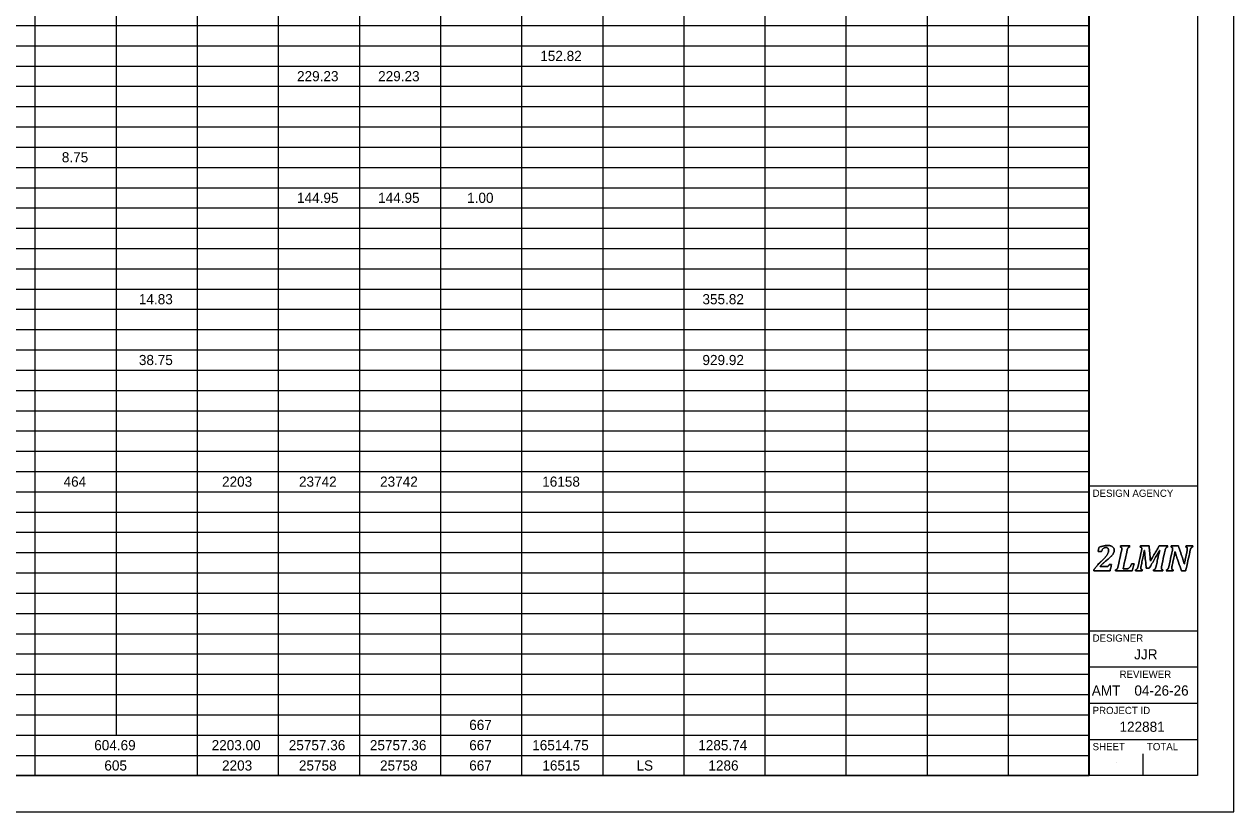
# Model space of a CAD drawing. Extents: x 0 to 34, y 0 to 22.
# Drawn here: x 17.3 to 34, y 0 to 10.88 of the extents above; entities that cross this region are included whole.
import ezdxf

# ---------------------------------------------------------------- set-up
doc = ezdxf.new("R2010")
doc.units = 0
for name, color, linetype in [('SH_Border', 7, 'Continuous'), ('SH_Cut_Line', 7, 'Continuous'), ('SH_Data', 7, 'Continuous'), ('SH_Text', 7, 'Continuous')]:
    doc.layers.add(name, color=color, linetype=linetype)

msp = doc.modelspace()

# ---------------------------------------------------------------- linework, layer by layer
at = {"layer": 'SH_Border'}
for p, q in [((32, 0.5), (32, 21.5)), ((32, 4.5), (33.5, 4.5)), ((32, 2.5), (33.5, 2.5)), ((32, 2), (33.5, 2)), ((32, 1.5), (33.5, 1.5)), ((32, 1), (33.5, 1))]:
    msp.add_line(p, q, dxfattribs=at)
msp.add_lwpolyline([(1.5, 21.5), (33.5, 21.5), (33.5, 0.5), (1.5, 0.5)], close=True, dxfattribs=at)
at = {"layer": 'SH_Cut_Line'}
msp.add_lwpolyline([(0, 0), (34, 0), (34, 22), (0, 22)], close=True, dxfattribs=at)
at = {"layer": 'SH_Data'}
for p, q in [((32.75, 3.5), (32.75, 3.5)), ((32.375, 0.675), (32.375, 0.675)), ((32.75, 0.5), (32.75, 0.8))]:
    msp.add_line(p, q, dxfattribs=at)
for points in [[(32.237, 3.388), (32.246, 3.388), (32.253, 3.389), (32.258, 3.39), (32.263, 3.392), (32.267, 3.394), (32.27, 3.397), (32.273, 3.401), (32.277, 3.408), (32.281, 3.417), (32.281, 3.417), (32.312, 3.417), (32.312, 3.417), (32.312, 3.417), (32.29, 3.326), (32.29, 3.326), (32.29, 3.326), (32.066, 3.326), (32.066, 3.326), (32.066, 3.326), (32.069, 3.343), (32.069, 3.343), (32.078, 3.358), (32.091, 3.375), (32.106, 3.394), (32.122, 3.412), (32.144, 3.435), (32.172, 3.462), (32.197, 3.486), (32.217, 3.506), (32.23, 3.521), (32.243, 3.537), (32.253, 3.551), (32.259, 3.566), (32.266, 3.58), (32.269, 3.595), (32.269, 3.61), (32.269, 3.622), (32.266, 3.632), (32.26, 3.64), (32.253, 3.647), (32.245, 3.65), (32.234, 3.65), (32.22, 3.65), (32.208, 3.646), (32.198, 3.636), (32.188, 3.627), (32.18, 3.613), (32.172, 3.593), (32.172, 3.593), (32.126, 3.593), (32.126, 3.593), (32.126, 3.593), (32.14, 3.654), (32.14, 3.654), (32.166, 3.663), (32.188, 3.669), (32.205, 3.673), (32.223, 3.676), (32.24, 3.678), (32.258, 3.678), (32.278, 3.678), (32.295, 3.675), (32.309, 3.669), (32.322, 3.664), (32.332, 3.656), (32.339, 3.646), (32.345, 3.637), (32.348, 3.626), (32.348, 3.613), (32.348, 3.602), (32.346, 3.591), (32.342, 3.581), (32.339, 3.571), (32.333, 3.56), (32.324, 3.549), (32.315, 3.539), (32.304, 3.526), (32.289, 3.513), (32.275, 3.499), (32.254, 3.482), (32.228, 3.46), (32.216, 3.45), (32.202, 3.438), (32.188, 3.425), (32.174, 3.412), (32.162, 3.4), (32.154, 3.391), (32.154, 3.391), (32.153, 3.388), (32.153, 3.388), (32.153, 3.388), (32.237, 3.388), (32.237, 3.388)], [(32.237, 3.388), (32.237, 3.388), (32.153, 3.388), (32.153, 3.388), (32.153, 3.388), (32.154, 3.391), (32.154, 3.391), (32.162, 3.4), (32.174, 3.412), (32.188, 3.425), (32.202, 3.438), (32.216, 3.45), (32.228, 3.46), (32.254, 3.482), (32.275, 3.499), (32.289, 3.513), (32.304, 3.526), (32.315, 3.539), (32.324, 3.549), (32.333, 3.56), (32.339, 3.571), (32.342, 3.581), (32.346, 3.591), (32.348, 3.602), (32.348, 3.613), (32.348, 3.626), (32.345, 3.637), (32.339, 3.646), (32.332, 3.656), (32.322, 3.664), (32.309, 3.669), (32.295, 3.675), (32.278, 3.678), (32.258, 3.678), (32.24, 3.678), (32.223, 3.676), (32.205, 3.673), (32.188, 3.669), (32.166, 3.663), (32.14, 3.654), (32.14, 3.654), (32.126, 3.593), (32.126, 3.593), (32.126, 3.593), (32.172, 3.593), (32.172, 3.593), (32.18, 3.613), (32.188, 3.627), (32.198, 3.636), (32.208, 3.646), (32.22, 3.65), (32.234, 3.65), (32.245, 3.65), (32.253, 3.647), (32.26, 3.64), (32.266, 3.632), (32.269, 3.622), (32.269, 3.61), (32.269, 3.595), (32.266, 3.58), (32.259, 3.566), (32.253, 3.551), (32.243, 3.537), (32.23, 3.521), (32.217, 3.506), (32.197, 3.486), (32.172, 3.462), (32.144, 3.435), (32.122, 3.412), (32.106, 3.394), (32.091, 3.375), (32.078, 3.358), (32.069, 3.343), (32.069, 3.343), (32.066, 3.326), (32.066, 3.326), (32.066, 3.326), (32.29, 3.326), (32.29, 3.326), (32.29, 3.326), (32.312, 3.417), (32.312, 3.417), (32.312, 3.417), (32.281, 3.417), (32.281, 3.417), (32.277, 3.408), (32.273, 3.401), (32.27, 3.397), (32.267, 3.394), (32.263, 3.392), (32.258, 3.39), (32.253, 3.389), (32.246, 3.388), (32.237, 3.388)], [(32.518, 3.356), (32.527, 3.356), (32.533, 3.357), (32.538, 3.358), (32.542, 3.36), (32.546, 3.362), (32.55, 3.365), (32.554, 3.368), (32.558, 3.372), (32.562, 3.377), (32.567, 3.382), (32.571, 3.388), (32.576, 3.397), (32.58, 3.405), (32.585, 3.415), (32.589, 3.427), (32.589, 3.427), (32.624, 3.427), (32.624, 3.427), (32.624, 3.427), (32.598, 3.326), (32.598, 3.326), (32.598, 3.326), (32.365, 3.326), (32.365, 3.326), (32.365, 3.326), (32.369, 3.343), (32.369, 3.343), (32.376, 3.345), (32.381, 3.348), (32.385, 3.351), (32.389, 3.355), (32.392, 3.36), (32.395, 3.366), (32.398, 3.373), (32.4, 3.382), (32.403, 3.395), (32.403, 3.395), (32.449, 3.605), (32.449, 3.605), (32.452, 3.615), (32.453, 3.625), (32.453, 3.635), (32.453, 3.642), (32.451, 3.647), (32.448, 3.651), (32.444, 3.654), (32.439, 3.656), (32.432, 3.657), (32.432, 3.657), (32.435, 3.674), (32.435, 3.674), (32.435, 3.674), (32.563, 3.674), (32.563, 3.674), (32.563, 3.674), (32.559, 3.657), (32.559, 3.657), (32.552, 3.655), (32.547, 3.652), (32.543, 3.649), (32.539, 3.645), (32.536, 3.64), (32.533, 3.634), (32.531, 3.627), (32.528, 3.618), (32.525, 3.605), (32.525, 3.605), (32.47, 3.356), (32.47, 3.356), (32.47, 3.356), (32.518, 3.356), (32.518, 3.356)], [(32.518, 3.356), (32.518, 3.356), (32.47, 3.356), (32.47, 3.356), (32.47, 3.356), (32.525, 3.605), (32.525, 3.605), (32.528, 3.618), (32.531, 3.627), (32.533, 3.634), (32.536, 3.64), (32.539, 3.645), (32.543, 3.649), (32.547, 3.652), (32.552, 3.655), (32.559, 3.657), (32.559, 3.657), (32.563, 3.674), (32.563, 3.674), (32.563, 3.674), (32.435, 3.674), (32.435, 3.674), (32.435, 3.674), (32.432, 3.657), (32.432, 3.657), (32.439, 3.656), (32.444, 3.654), (32.448, 3.651), (32.451, 3.647), (32.453, 3.642), (32.453, 3.635), (32.453, 3.625), (32.452, 3.615), (32.449, 3.605), (32.449, 3.605), (32.403, 3.395), (32.403, 3.395), (32.4, 3.382), (32.398, 3.373), (32.395, 3.366), (32.392, 3.36), (32.389, 3.355), (32.385, 3.351), (32.381, 3.348), (32.376, 3.345), (32.369, 3.343), (32.369, 3.343), (32.365, 3.326), (32.365, 3.326), (32.365, 3.326), (32.598, 3.326), (32.598, 3.326), (32.598, 3.326), (32.624, 3.427), (32.624, 3.427), (32.624, 3.427), (32.589, 3.427), (32.589, 3.427), (32.585, 3.415), (32.58, 3.405), (32.576, 3.397), (32.571, 3.388), (32.567, 3.382), (32.562, 3.377), (32.558, 3.372), (32.554, 3.368), (32.55, 3.365), (32.546, 3.362), (32.542, 3.36), (32.538, 3.358), (32.533, 3.357), (32.527, 3.356), (32.518, 3.356)], [(32.829, 3.674), (32.829, 3.674), (32.849, 3.461), (32.849, 3.461), (32.849, 3.461), (32.969, 3.674), (32.969, 3.674), (32.969, 3.674), (33.087, 3.674), (33.087, 3.674), (33.087, 3.674), (33.084, 3.657), (33.084, 3.657), (33.077, 3.655), (33.071, 3.652), (33.067, 3.649), (33.064, 3.645), (33.06, 3.64), (33.058, 3.634), (33.055, 3.627), (33.052, 3.618), (33.05, 3.605), (33.05, 3.605), (33.003, 3.395), (33.003, 3.395), (33.002, 3.39), (33.002, 3.387), (33.001, 3.384), (33.001, 3.382), (33.001, 3.379), (33, 3.376), (33, 3.373), (33, 3.369), (33, 3.365), (33, 3.358), (33.002, 3.353), (33.005, 3.349), (33.008, 3.346), (33.014, 3.344), (33.021, 3.343), (33.021, 3.343), (33.018, 3.326), (33.018, 3.326), (33.018, 3.326), (32.89, 3.326), (32.89, 3.326), (32.89, 3.326), (32.893, 3.343), (32.893, 3.343), (32.9, 3.345), (32.906, 3.348), (32.91, 3.351), (32.914, 3.355), (32.917, 3.36), (32.919, 3.366), (32.922, 3.373), (32.925, 3.382), (32.928, 3.395), (32.928, 3.395), (32.951, 3.502), (32.951, 3.502), (32.954, 3.513), (32.957, 3.529), (32.962, 3.548), (32.967, 3.568), (32.972, 3.588), (32.978, 3.609), (32.978, 3.609), (32.973, 3.609), (32.973, 3.609), (32.965, 3.594), (32.957, 3.579), (32.948, 3.563), (32.948, 3.563), (32.833, 3.364), (32.833, 3.364), (32.833, 3.364), (32.792, 3.364), (32.792, 3.364), (32.792, 3.364), (32.775, 3.518), (32.775, 3.518), (32.773, 3.537), (32.772, 3.554), (32.77, 3.569), (32.769, 3.583), (32.768, 3.597), (32.768, 3.611), (32.768, 3.611), (32.764, 3.611), (32.764, 3.611), (32.761, 3.596), (32.758, 3.578), (32.755, 3.558), (32.751, 3.538), (32.747, 3.521), (32.744, 3.507), (32.744, 3.507), (32.72, 3.395), (32.72, 3.395), (32.719, 3.39), (32.718, 3.387), (32.718, 3.384), (32.717, 3.382), (32.717, 3.379), (32.717, 3.376), (32.717, 3.373), (32.716, 3.369), (32.716, 3.365), (32.716, 3.358), (32.718, 3.353), (32.721, 3.349), (32.725, 3.346), (32.73, 3.344), (32.738, 3.343), (32.738, 3.343), (32.734, 3.326), (32.734, 3.326), (32.734, 3.326), (32.641, 3.326), (32.641, 3.326), (32.641, 3.326), (32.644, 3.343), (32.644, 3.343), (32.651, 3.345), (32.657, 3.348), (32.661, 3.351), (32.665, 3.355), (32.668, 3.36), (32.67, 3.366), (32.673, 3.373), (32.676, 3.382), (32.679, 3.395), (32.679, 3.395), (32.725, 3.605), (32.725, 3.605), (32.727, 3.615), (32.728, 3.625), (32.728, 3.635), (32.728, 3.642), (32.727, 3.647), (32.723, 3.651), (32.72, 3.654), (32.715, 3.656), (32.707, 3.657), (32.707, 3.657), (32.711, 3.674), (32.711, 3.674), (32.711, 3.674), (32.829, 3.674), (32.829, 3.674)], [(32.829, 3.674), (32.829, 3.674), (32.711, 3.674), (32.711, 3.674), (32.711, 3.674), (32.707, 3.657), (32.707, 3.657), (32.715, 3.656), (32.72, 3.654), (32.723, 3.651), (32.727, 3.647), (32.728, 3.642), (32.728, 3.635), (32.728, 3.625), (32.727, 3.615), (32.725, 3.605), (32.725, 3.605), (32.679, 3.395), (32.679, 3.395), (32.676, 3.382), (32.673, 3.373), (32.67, 3.366), (32.668, 3.36), (32.665, 3.355), (32.661, 3.351), (32.657, 3.348), (32.651, 3.345), (32.644, 3.343), (32.644, 3.343), (32.641, 3.326), (32.641, 3.326), (32.641, 3.326), (32.734, 3.326), (32.734, 3.326), (32.734, 3.326), (32.738, 3.343), (32.738, 3.343), (32.73, 3.344), (32.725, 3.346), (32.721, 3.349), (32.718, 3.353), (32.716, 3.358), (32.716, 3.365), (32.716, 3.369), (32.717, 3.373), (32.717, 3.376), (32.717, 3.379), (32.717, 3.382), (32.718, 3.384), (32.718, 3.387), (32.719, 3.39), (32.72, 3.395), (32.72, 3.395), (32.744, 3.507), (32.744, 3.507), (32.747, 3.521), (32.751, 3.538), (32.755, 3.558), (32.758, 3.578), (32.761, 3.596), (32.764, 3.611), (32.764, 3.611), (32.768, 3.611), (32.768, 3.611), (32.768, 3.597), (32.769, 3.583), (32.77, 3.569), (32.772, 3.554), (32.773, 3.537), (32.775, 3.518), (32.775, 3.518), (32.792, 3.364), (32.792, 3.364), (32.792, 3.364), (32.833, 3.364), (32.833, 3.364), (32.833, 3.364), (32.948, 3.563), (32.948, 3.563), (32.957, 3.579), (32.965, 3.594), (32.973, 3.609), (32.973, 3.609), (32.978, 3.609), (32.978, 3.609), (32.972, 3.588), (32.967, 3.568), (32.962, 3.548), (32.957, 3.529), (32.954, 3.513), (32.951, 3.502), (32.951, 3.502), (32.928, 3.395), (32.928, 3.395), (32.925, 3.382), (32.922, 3.373), (32.919, 3.366), (32.917, 3.36), (32.914, 3.355), (32.91, 3.351), (32.906, 3.348), (32.9, 3.345), (32.893, 3.343), (32.893, 3.343), (32.89, 3.326), (32.89, 3.326), (32.89, 3.326), (33.018, 3.326), (33.018, 3.326), (33.018, 3.326), (33.021, 3.343), (33.021, 3.343), (33.014, 3.344), (33.008, 3.346), (33.005, 3.349), (33.002, 3.353), (33, 3.358), (33, 3.365), (33, 3.369), (33, 3.373), (33, 3.376), (33.001, 3.379), (33.001, 3.382), (33.001, 3.384), (33.002, 3.387), (33.002, 3.39), (33.003, 3.395), (33.003, 3.395), (33.05, 3.605), (33.05, 3.605), (33.052, 3.618), (33.055, 3.627), (33.058, 3.634), (33.06, 3.64), (33.064, 3.645), (33.067, 3.649), (33.071, 3.652), (33.077, 3.655), (33.084, 3.657), (33.084, 3.657), (33.087, 3.674), (33.087, 3.674), (33.087, 3.674), (32.969, 3.674), (32.969, 3.674), (32.969, 3.674), (32.849, 3.461), (32.849, 3.461), (32.849, 3.461), (32.829, 3.674), (32.829, 3.674)], [(33.137, 3.674), (33.137, 3.674), (33.234, 3.674), (33.234, 3.674), (33.234, 3.674), (33.283, 3.53), (33.283, 3.53), (33.296, 3.49), (33.307, 3.456), (33.315, 3.426), (33.315, 3.426), (33.318, 3.426), (33.318, 3.426), (33.323, 3.455), (33.329, 3.488), (33.337, 3.523), (33.337, 3.523), (33.355, 3.605), (33.355, 3.605), (33.357, 3.615), (33.358, 3.625), (33.358, 3.635), (33.358, 3.642), (33.357, 3.647), (33.353, 3.651), (33.35, 3.654), (33.345, 3.656), (33.337, 3.657), (33.337, 3.657), (33.341, 3.674), (33.341, 3.674), (33.341, 3.674), (33.434, 3.674), (33.434, 3.674), (33.434, 3.674), (33.431, 3.657), (33.431, 3.657), (33.424, 3.655), (33.418, 3.652), (33.414, 3.649), (33.41, 3.645), (33.407, 3.64), (33.405, 3.634), (33.402, 3.627), (33.399, 3.618), (33.396, 3.605), (33.396, 3.605), (33.335, 3.326), (33.335, 3.326), (33.335, 3.326), (33.277, 3.326), (33.277, 3.326), (33.277, 3.326), (33.216, 3.504), (33.216, 3.504), (33.211, 3.518), (33.207, 3.531), (33.204, 3.543), (33.2, 3.556), (33.195, 3.571), (33.19, 3.59), (33.19, 3.59), (33.186, 3.59), (33.186, 3.59), (33.185, 3.579), (33.182, 3.563), (33.179, 3.543), (33.175, 3.523), (33.17, 3.501), (33.165, 3.478), (33.165, 3.478), (33.147, 3.395), (33.147, 3.395), (33.146, 3.39), (33.145, 3.387), (33.145, 3.384), (33.144, 3.382), (33.144, 3.379), (33.144, 3.376), (33.143, 3.373), (33.143, 3.369), (33.143, 3.365), (33.143, 3.358), (33.145, 3.353), (33.148, 3.349), (33.152, 3.346), (33.157, 3.344), (33.164, 3.343), (33.164, 3.343), (33.161, 3.326), (33.161, 3.326), (33.161, 3.326), (33.067, 3.326), (33.067, 3.326), (33.067, 3.326), (33.071, 3.343), (33.071, 3.343), (33.078, 3.345), (33.083, 3.348), (33.087, 3.351), (33.091, 3.355), (33.094, 3.36), (33.097, 3.366), (33.1, 3.373), (33.102, 3.382), (33.105, 3.395), (33.105, 3.395), (33.151, 3.605), (33.151, 3.605), (33.154, 3.615), (33.155, 3.625), (33.155, 3.635), (33.155, 3.642), (33.153, 3.647), (33.15, 3.651), (33.146, 3.654), (33.141, 3.656), (33.134, 3.657), (33.134, 3.657), (33.137, 3.674), (33.137, 3.674)], [(33.137, 3.674), (33.137, 3.674), (33.134, 3.657), (33.134, 3.657), (33.141, 3.656), (33.146, 3.654), (33.15, 3.651), (33.153, 3.647), (33.155, 3.642), (33.155, 3.635), (33.155, 3.625), (33.154, 3.615), (33.151, 3.605), (33.151, 3.605), (33.105, 3.395), (33.105, 3.395), (33.102, 3.382), (33.1, 3.373), (33.097, 3.366), (33.094, 3.36), (33.091, 3.355), (33.087, 3.351), (33.083, 3.348), (33.078, 3.345), (33.071, 3.343), (33.071, 3.343), (33.067, 3.326), (33.067, 3.326), (33.067, 3.326), (33.161, 3.326), (33.161, 3.326), (33.161, 3.326), (33.164, 3.343), (33.164, 3.343), (33.157, 3.344), (33.152, 3.346), (33.148, 3.349), (33.145, 3.353), (33.143, 3.358), (33.143, 3.365), (33.143, 3.369), (33.143, 3.373), (33.144, 3.376), (33.144, 3.379), (33.144, 3.382), (33.145, 3.384), (33.145, 3.387), (33.146, 3.39), (33.147, 3.395), (33.147, 3.395), (33.165, 3.478), (33.165, 3.478), (33.17, 3.501), (33.175, 3.523), (33.179, 3.543), (33.182, 3.563), (33.185, 3.579), (33.186, 3.59), (33.186, 3.59), (33.19, 3.59), (33.19, 3.59), (33.195, 3.571), (33.2, 3.556), (33.204, 3.543), (33.207, 3.531), (33.211, 3.518), (33.216, 3.504), (33.216, 3.504), (33.277, 3.326), (33.277, 3.326), (33.277, 3.326), (33.335, 3.326), (33.335, 3.326), (33.335, 3.326), (33.396, 3.605), (33.396, 3.605), (33.399, 3.618), (33.402, 3.627), (33.405, 3.634), (33.407, 3.64), (33.41, 3.645), (33.414, 3.649), (33.418, 3.652), (33.424, 3.655), (33.431, 3.657), (33.431, 3.657), (33.434, 3.674), (33.434, 3.674), (33.434, 3.674), (33.341, 3.674), (33.341, 3.674), (33.341, 3.674), (33.337, 3.657), (33.337, 3.657), (33.345, 3.656), (33.35, 3.654), (33.353, 3.651), (33.357, 3.647), (33.358, 3.642), (33.358, 3.635), (33.358, 3.625), (33.357, 3.615), (33.355, 3.605), (33.355, 3.605), (33.337, 3.523), (33.337, 3.523), (33.329, 3.488), (33.323, 3.455), (33.318, 3.426), (33.318, 3.426), (33.315, 3.426), (33.315, 3.426), (33.307, 3.456), (33.296, 3.49), (33.283, 3.53), (33.283, 3.53), (33.234, 3.674), (33.234, 3.674), (33.234, 3.674), (33.137, 3.674), (33.137, 3.674)]]:
    msp.add_open_spline(points, degree=3, dxfattribs=at)
at = {"layer": 'SH_Text'}
for p, q in [((17.444, 21.5), (17.444, 0.5)), ((18.564, 21.5), (18.564, 1.06)), ((19.684, 21.5), (19.684, 0.5)), ((20.804, 21.5), (20.804, 0.5)), ((21.924, 21.5), (21.924, 0.5)), ((23.044, 21.5), (23.044, 0.5)), ((24.164, 21.5), (24.164, 0.5)), ((25.284, 21.5), (25.284, 0.5)), ((26.404, 21.5), (26.404, 0.5)), ((27.524, 21.5), (27.524, 0.5)), ((28.644, 21.5), (28.644, 0.5)), ((29.764, 21.5), (29.764, 0.5)), ((30.884, 21.5), (30.884, 0.5)), ((32.004, 21.5), (32.004, 0.5)), ((1.5, 10.86), (32.004, 10.86)), ((1.5, 10.58), (32.004, 10.58)), ((1.5, 10.3), (32.004, 10.3)), ((1.5, 10.02), (32.004, 10.02)), ((1.5, 9.74), (32.004, 9.74)), ((1.5, 9.46), (32.004, 9.46)), ((1.5, 9.18), (32.004, 9.18)), ((1.5, 8.9), (32.004, 8.9)), ((1.5, 8.62), (32.004, 8.62)), ((1.5, 8.34), (32.004, 8.34)), ((1.5, 8.06), (32.004, 8.06)), ((1.5, 7.78), (32.004, 7.78)), ((1.5, 7.5), (32.004, 7.5)), ((1.5, 7.22), (32.004, 7.22)), ((1.5, 6.94), (32.004, 6.94)), ((1.5, 6.66), (32.004, 6.66)), ((1.5, 6.38), (32.004, 6.38)), ((1.5, 6.1), (32.004, 6.1)), ((1.5, 5.82), (32.004, 5.82)), ((1.5, 5.54), (32.004, 5.54)), ((1.5, 5.26), (32.004, 5.26)), ((1.5, 4.98), (32.004, 4.98)), ((1.5, 4.7), (32.004, 4.7)), ((1.5, 4.42), (32.004, 4.42)), ((1.5, 4.14), (32.004, 4.14)), ((1.5, 3.86), (32.004, 3.86)), ((1.5, 3.58), (32.004, 3.58)), ((1.5, 3.3), (32.004, 3.3)), ((1.5, 3.02), (32.004, 3.02)), ((1.5, 2.74), (32.004, 2.74)), ((1.5, 2.46), (32.004, 2.46)), ((1.5, 2.18), (32.004, 2.18)), ((1.5, 1.9), (32.004, 1.9)), ((1.5, 1.62), (32.004, 1.62)), ((1.5, 1.34), (32.004, 1.34)), ((1.5, 1.06), (32.004, 1.06)), ((1.5, 0.78), (32.004, 0.78)), ((1.5, 0.5), (32.004, 0.5))]:
    msp.add_line(p, q, dxfattribs=at)

# ---------------------------------------------------------------- texts
at = {"layer": 'SH_Data'}
for s, height, p in [('DESIGN AGENCY', 0.1, (32.05, 4.35)), ('DESIGNER', 0.1, (32.05, 2.35)), ('JJR', 0.14, (32.624, 2.105)), ('REVIEWER', 0.1, (32.422, 1.85)), ('AMT', 0.14, (32.039, 1.605)), ('04-26-26', 0.14, (32.627, 1.605)), ('PROJECT ID', 0.1, (32.05, 1.35)), ('122881', 0.14, (32.421, 1.105)), ('SHEET', 0.1, (32.05, 0.85)), ('TOTAL', 0.1, (32.8, 0.85))]:
    msp.add_text(s, height=height, dxfattribs=at).set_placement(p)
at = {"layer": 'SH_Text'}
for s, p in [('152.82', (24.422, 10.37)), ('229.23', (21.063, 10.09)), ('229.23', (22.183, 10.09)), ('8.75', (17.815, 8.97)), ('144.95', (21.063, 8.41)), ('144.95', (22.183, 8.41)), ('1.00', (23.412, 8.41)), ('14.83', (18.879, 7.01)), ('355.82', (26.662, 7.01)), ('38.75', (18.879, 6.17)), ('929.92', (26.662, 6.17)), ('464', (17.839, 4.49)), ('2203', (20.027, 4.49)), ('23742', (21.09, 4.49)), ('23742', (22.21, 4.49)), ('16158', (24.449, 4.49)), ('667', (23.441, 1.13)), ('604.69', (18.262, 0.85)), ('2203.00', (19.884, 0.85)), ('25757.36', (20.949, 0.85)), ('25757.36', (22.069, 0.85)), ('667', (23.441, 0.85)), ('16514.75', (24.311, 0.85)), ('1285.74', (26.604, 0.85)), ('605', (18.402, 0.57)), ('2203', (20.027, 0.57)), ('25758', (21.089, 0.57)), ('25758', (22.209, 0.57)), ('667', (23.441, 0.57)), ('16515', (24.451, 0.57)), ('LS', (25.751, 0.57)), ('1286', (26.744, 0.57))]:
    msp.add_text(s, height=0.14, dxfattribs=at).set_placement(p)

doc.saveas('drawing.dxf')
